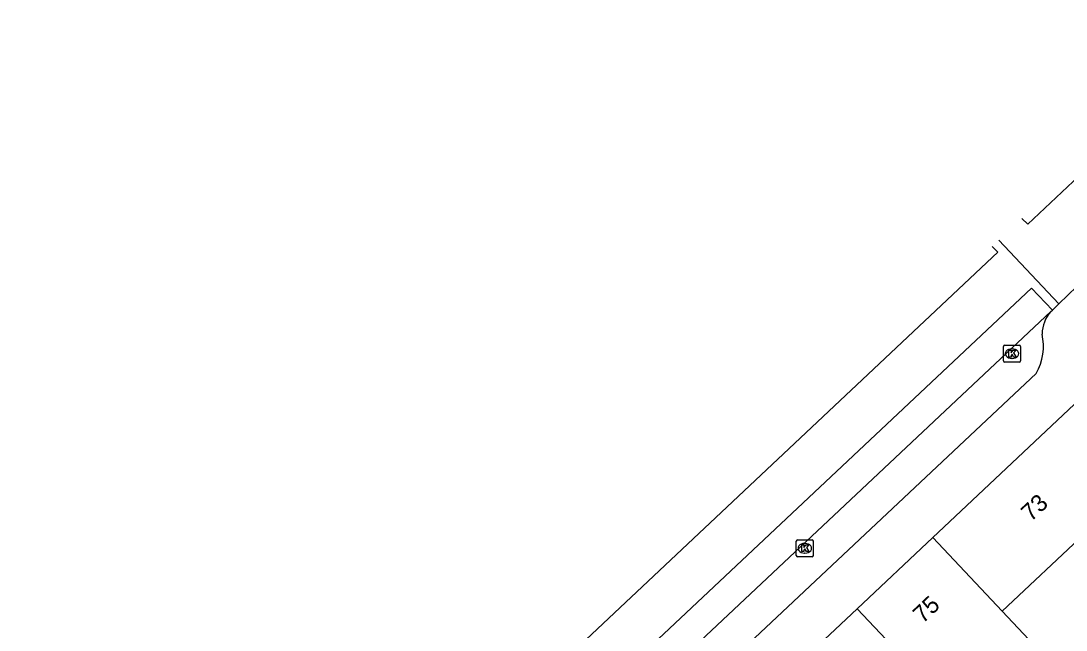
# Model space of a CAD drawing. Extents: x 162542 to 163144, y 380786 to 381511.
# Drawn here: x 162562.1 to 162623.6, y 381265.7 to 381301.5 of the extents above; entities that cross this region are included whole.
import ezdxf

# ---------------------------------------------------------------- set-up
doc = ezdxf.new("R2010")
doc.units = 0
for name, color, linetype in [('IMGEO_Kolk', 7, 'Continuous'), ('IMGEO_Pand', 7, 'Continuous'), ('IMGEO_Pand_nummerreeks', 7, 'Continuous'), ('IMGEO_Rijbaan_lokaal_gesloten', 7, 'Continuous'), ('IMGEO_Rijbaan_lokaal_open', 7, 'Continuous'), ('IMGEO_Voetpad_open', 7, 'Continuous')]:
    doc.layers.add(name, color=color, linetype=linetype)

msp = doc.modelspace()

# ---------------------------------------------------------------- linework, layer by layer
at = {"layer": 'IMGEO_Kolk'}
for p, q in [((162619.932, 381281.517), (162619.932, 381282.369)), ((162620.007, 381282.443), (162620.859, 381282.443)), ((162620.933, 381282.369), (162620.933, 381281.517)), ((162620.42, 381282.223), (162620.445, 381282.223)), ((162620.859, 381281.443), (162620.007, 381281.443)), ((162620.443, 381281.663), (162620.418, 381281.663)), ((162607.748, 381270.075), (162607.748, 381270.927)), ((162607.823, 381271.001), (162608.675, 381271.001)), ((162608.236, 381270.781), (162608.261, 381270.781)), ((162608.749, 381270.927), (162608.749, 381270.075)), ((162608.259, 381270.221), (162608.234, 381270.221)), ((162608.675, 381270.001), (162607.823, 381270.001))]:
    msp.add_line(p, q, dxfattribs=at)
for points in [[(162619.932, 381281.517), (162619.932, 381282.369)], [(162620.007, 381282.443), (162620.859, 381282.443)], [(162620.933, 381282.369), (162620.933, 381281.517)], [(162620.253, 381282.143), (162620.376, 381282.143), (162620.376, 381281.992), (162620.506, 381282.143), (162620.67, 381282.143), (162620.524, 381281.992), (162620.677, 381281.743), (162620.525, 381281.743), (162620.44, 381281.907), (162620.376, 381281.84), (162620.376, 381281.743), (162620.253, 381281.743), (162620.253, 381282.143)], [(162620.859, 381281.443), (162620.007, 381281.443)], [(162607.748, 381270.075), (162607.748, 381270.927)], [(162607.823, 381271.001), (162608.675, 381271.001)], [(162608.069, 381270.701), (162608.192, 381270.701), (162608.192, 381270.55), (162608.322, 381270.701), (162608.486, 381270.701), (162608.34, 381270.55), (162608.493, 381270.301), (162608.341, 381270.301), (162608.256, 381270.465), (162608.192, 381270.398), (162608.192, 381270.301), (162608.069, 381270.301), (162608.069, 381270.701)], [(162608.749, 381270.927), (162608.749, 381270.075)], [(162608.675, 381270.001), (162607.823, 381270.001)]]:
    msp.add_lwpolyline(points, dxfattribs=at)
for centre, start, end in [((162620.009, 381282.367), 91.55205, 178.44795), ((162620.009, 381282.367), 91.55205, 178.44795), ((162620.857, 381282.367), 1.55205, 88.44795), ((162620.857, 381282.367), 1.55205, 88.44795), ((162620.009, 381281.519), 181.55205, 268.44795), ((162620.009, 381281.519), 181.55205, 268.44795), ((162620.857, 381281.519), 271.55205, 358.44795), ((162620.857, 381281.519), 271.55205, 358.44795), ((162607.825, 381270.925), 91.55205, 178.44795), ((162607.825, 381270.925), 91.55205, 178.44795), ((162608.673, 381270.925), 1.55205, 88.44795), ((162608.673, 381270.925), 1.55205, 88.44795), ((162607.825, 381270.077), 181.55205, 268.44795), ((162607.825, 381270.077), 181.55205, 268.44795), ((162608.673, 381270.077), 271.55205, 358.44795), ((162608.673, 381270.077), 271.55205, 358.44795)]:
    msp.add_arc(centre, 0.0765, start, end, dxfattribs=at)
for centre, major_axis, ratio, start_param, end_param in [((162620.419, 381281.943), (-0.387, 0.002), 0.722429, 4.712389, 7.853982), ((162620.444, 381281.943), (-0.39, 0.002), 0.717154, 1.570796, 4.712389), ((162608.235, 381270.501), (-0.387, 0.002), 0.722429, 4.712389, 7.853982), ((162608.26, 381270.501), (-0.39, 0.002), 0.717154, 1.570796, 4.712389)]:
    msp.add_ellipse(centre, major_axis=major_axis, ratio=ratio, start_param=start_param, end_param=end_param, dxfattribs=at)
at = {"layer": 'IMGEO_Pand'}
for points in [[(162624.093, 381278.942), (162615.787, 381271.127)], [(162619.859, 381266.803), (162624.695, 381271.355)], [(162615.787, 381271.127), (162611.337, 381266.938)], [(162615.787, 381271.127), (162619.859, 381266.803)], [(162613.358, 381264.79), (162611.337, 381266.938)], [(162618.56, 381259.935), (162622.677, 381263.811), (162619.859, 381266.803)]]:
    msp.add_lwpolyline(points, dxfattribs=at)
at = {"layer": 'IMGEO_Rijbaan_lokaal_gesloten'}
for points in [[(162633.362, 381301.5), (162633.69, 381301.157), (162621.357, 381289.553), (162621.016, 381289.891)], [(162563.535, 381235.177), (162619.602, 381287.9), (162619.267, 381288.247)], [(162565.547, 381233.139), (162621.587, 381285.788), (162622.812, 381284.503)], [(162566.775, 381231.855), (162622.72, 381284.415)], [(162622.72, 381284.415), (162622.812, 381284.503)]]:
    msp.add_lwpolyline(points, dxfattribs=at)
at = {"layer": 'IMGEO_Rijbaan_lokaal_open'}
for points in [[(162623.196, 381284.872), (162619.656, 381288.613)], [(162623.196, 381284.872), (162624.252, 381285.886)], [(162622.812, 381284.503), (162623.196, 381284.872)]]:
    msp.add_lwpolyline(points, dxfattribs=at)
at = {"layer": 'IMGEO_Voetpad_open'}
for points in [[(162562.146, 381224.688), (162621.86, 381280.778)], [(162611.337, 381266.938), (162593.265, 381250), (162581.55, 381238.977)]]:
    msp.add_lwpolyline(points, dxfattribs=at)
for centre, radius, start, end in [((162624.202, 381283.07), 2.001, 137.78109, 179.37973), ((162619.068, 381282.372), 3.215, 330.2867, 12.94731)]:
    msp.add_arc(centre, radius, start, end, dxfattribs=at)

# ---------------------------------------------------------------- texts
at = {"layer": 'IMGEO_Pand_nummerreeks'}
for s, rotation, p in [('73', 43.03558, (162621.544, 381272.031)), ('75', 43.36266, (162615.187, 381266.046))]:
    msp.add_text(s, height=1, rotation=rotation, dxfattribs=at).set_placement(p)

doc.saveas('drawing.dxf')
